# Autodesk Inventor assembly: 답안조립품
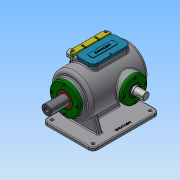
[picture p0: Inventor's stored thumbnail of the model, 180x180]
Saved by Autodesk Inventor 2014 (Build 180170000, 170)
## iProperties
Created: 2018-08
Part Number: 답안조립품
Document SubType Name: Assembly
Designer: net
Author: net
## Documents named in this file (15)
- C:\Users\net\Desktop\380807V1021\380807V1021\답안조립품.iam
- C:\Users\net\Desktop\380807V1021\380807V1021\본체.ipt
- C:\Users\net\Desktop\380807V1021\380807V1021\편심축.ipt
- C:\Users\net\Desktop\380807V1021\380807V1021\베어링 6205.ipt
- 베어링 6205.ipt
- C:\Users\net\Desktop\380807V1021\380807V1021\축 커버.ipt
- C:\Users\net\Desktop\380807V1021\380807V1021\볼트 M4x0.7.ipt
- C:\Users\net\Desktop\380807V1021\380807V1021\오일 실 25 38 8.ipt
- C:\Users\net\Desktop\380807V1021\380807V1021\상부커버.ipt
- C:\Users\net\Desktop\380807V1021\380807V1021\고정플레이트.ipt
- C:\Users\net\Desktop\380807V1021\380807V1021\육각머리볼트 M4.ipt
- C:\Users\net\Desktop\380807V1021\380807V1021\슬라이드.ipt
- C:\Users\net\Desktop\380807V1021\380807V1021\슬라이드 커버.ipt
- C:\Users\net\Desktop\380807V1021\380807V1021\부시.ipt
- C:\Users\net\Desktop\380807V1021\380807V1021\가변스프링.ipt
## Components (14 placed, 3 different names)
1. 고정플레이트:1
2. 가변스프링:1
3. M4x0.7:1
4. M4x0.7:3
5. M4x0.7:4
6. M4x0.7:5
7. M4x0.7:2
8. M4x0.7:6
9. M4x0.7:7
10. M4x0.7:8
11. M4x0.7:9
12. M4x0.7:10
13. M4x0.7:11
14. M4x0.7:12
